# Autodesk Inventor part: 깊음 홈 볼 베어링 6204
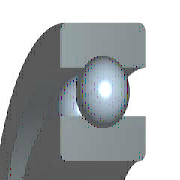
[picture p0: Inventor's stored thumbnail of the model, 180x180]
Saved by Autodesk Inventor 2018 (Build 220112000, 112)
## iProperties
IsCustomPart: 1
Created: 2012-02
Part Number: 깊음 홈 볼 베어링 6204
Material: 강철, 연강
Description: 깊은 그루부 볼 베어링
Document SubType Name: Modeling
Standard: JIS B 1521
Designer: mdu-01
Standards Organization: JIS
Language: ko-KR
Size Designation: 6204 20x47x14
Categories: <MemberInstance><Categories><Category DisplayName="샤프트 부품" InternalName="7f7aeb1f-a693-4053-b835-cee3144e0d98" Mnemonic="SHFT"><Category DisplayName="베어링" Inter
Density: 1 g/cm^3
Appearance: 강철(1)
Author: mdu-01
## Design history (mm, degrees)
sketch "스케치" dims "d0" = 7.02 (= -0.26 x WD + 0.26 x BD)
  geometry: L1 (3.49, 16.75)-(10.51, 16.75); L2 (7, 16.75)-(7, 13.24); L3 (7, 16.75)-(7, 20.26); L4 (4.392, 14.401)-(0, 14.401); L5 (0, 10)-(14, 10); L6 (4.392, 19.099)-(0, 19.099); L7 (0, 23.5)-(14, 23.5); L8 (14, 10)-(14, 14.401); L9 (9.608, 14.401)-(14, 14.401); L10 (9.608, 19.099)-(14, 19.099); L11 (14, 23.5)-(14, 19.099); L12 (-1.4, 0)-(8.4, 0) reference; L13 (0, -0.3)-(0, 5.3) reference
  constraints: 22 end point, 4 point on line, 2 collinear, 2 perpendicular, 2 symmetric about line, 1 midpoint, 1 parallel, 14 other
  dimensions: "d9" = 20 diameter of L5 L12 (= WD); "d11" = 47 diameter of L7 L12 (= BD); "d12" = 14 distance between parallel lines of L8 L13 (= KB); "d13" = 28.802 diameter of L9 L12 (= 0.326 x BD + 0.674 x WD)
revolve "본체" stored, may be unused: angle "d6" = 90 deg
revolve "볼" stored, may be unused: angle "d7" = 90 deg
pattern_circular "IDS_ARRAYBALL[SIMPL:T]" dims angle "d3" = 360 deg
body "Solid1"
fillet "모깎기1" dims "d1" = 1 (= KRS)
other parameters: "WD" = 20 [user parameter; used in 5 equation terms], "BD" = 47 [user parameter; used in 5 equation terms], "KB" = 14 [user parameter; used in 1 equation term], "KRS" = 1 [user parameter; used in 1 equation term], "d4" = 0, "d5" = 0, "d8" = 0, "d14" = 0, "d15" = 0, "BBA" = 0 [user parameter], "BC0" = 6550000 [user parameter], "BC" = 1.27e+07 [user parameter], "BR" = 23.5 (= 0.5 x BD) [user parameter]
